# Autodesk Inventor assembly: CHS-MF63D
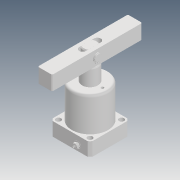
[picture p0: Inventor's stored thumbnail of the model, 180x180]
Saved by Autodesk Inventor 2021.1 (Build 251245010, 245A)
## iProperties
Created: 2019-05
Part Number: CHS-MF63D
Description: STEP AP203
Document SubType Name: Assembly
Designer: user
Title: chs-mf63d_asm.STEP
Revision Number: ÈÎºÎ
Sending System: SolidWorks 2017
Preprocessor: SwSTEP 2.0
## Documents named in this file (10)
- D:\Vault_2016\Projekty\Clamptek\Hydraulic\CHS\CHS-63\Inventor\CHS-MF63D\CHS-MF63D.iam
- D:\Vault_2016\Projekty\Clamptek\Hydraulic\CHS\CHS-63\Inventor\CHS-MF63D\CHS-MF63-03.ipt
- D:\Vault_2016\Projekty\Clamptek\Hydraulic\CHS\CHS-63\Inventor\CHS-MF63D\CHS-63D-01_2.ipt
- D:\Vault_2016\Projekty\Clamptek\Hydraulic\CHS\CHS-63\Inventor\CHS-MF63D\CHS-TXF-01.ipt
- D:\Vault_2016\Projekty\Clamptek\Hydraulic\CHS\CHS-63\Inventor\CHS-MF63D\CHS-MF40-TXF-03.ipt
- D:\Vault_2016\Projekty\Clamptek\Hydraulic\CHS\CHS-63\Inventor\CHS-MF63D\CHS-MF40-TXF-02.ipt
- D:\Vault_2016\Projekty\Clamptek\Hydraulic\CHS\CHS-63\Inventor\CHS-MF63D\M6.ipt
- D:\Vault_2016\Projekty\Clamptek\Hydraulic\CHS\CHS-63\Inventor\CHS-MF63D\CHS-63D»îÈû¸Ë_4.ipt
- D:\Vault_2016\Projekty\Clamptek\Hydraulic\CHS\CHS-63\Inventor\CHS-MF63D\¶ÌÏú.ipt
- D:\Vault_2016\Projekty\Clamptek\Hydraulic\CHS\CHS-63\Inventor\CHS-MF63D\¿¨»É.ipt
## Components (10 placed, 10 different names)
1. CHS-MF63-03_1
2. CHS-63D-01_2_2
3. CHS-TXF-01_3
4. CHS-MF40-TXF-03_4
5. CHS-MF40-TXF-02_5
6. M6_6
7. CHS-63D»îÈû¸Ë_4_7
8. ¶ÌÏú_8
9. ¿¨»É_9
10. ¿¨»É_10
